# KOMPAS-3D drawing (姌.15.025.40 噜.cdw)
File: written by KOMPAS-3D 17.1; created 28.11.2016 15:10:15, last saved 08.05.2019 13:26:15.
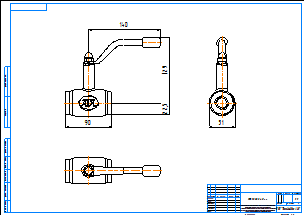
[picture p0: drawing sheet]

Sheet 1: A2, landscape

Title block, sheet 1: name: КШ.15.025.40 рр; material: Внимание! Данный продукт является объектом авторского права ООО «Торговый Дом АДЛ». / Запрещается изменение, копирование, распространение / (в том числе путем копирования на другие сайты и ресурсы в Интернете) / или любое иное использование информации и объектов без предварительного / согласия правообладателя (ООО «Торговый Дом АДЛ»).; sheets: 1; organisation: ООО "Торговый дом АДЛ"; sheet format: A2; stored path: C:\Users\tra\Desktop\2д чертежи\Шаровые краны БИВАЛ\КШ_Бивал_серия_14_15\KOMPAS_2D\КШ.15.025.40 рр.cdw

Views: Вид 1, Проекционный вид 2, Проекционный вид 3
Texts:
  Klimkovich
  ADL
Dimensions and other numbers on the sheet: 90; 140; 129; 22,5; 51; 1:1; 1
